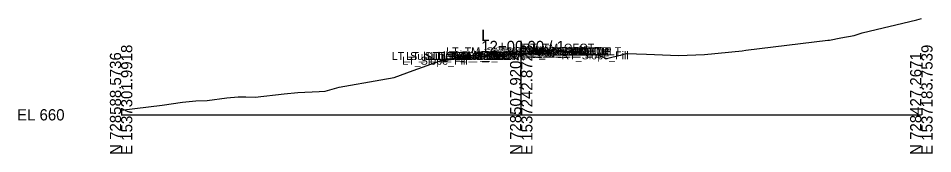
# Model space of a CAD drawing. Extents: x -26 to 1203, y -10 to 9522.
# Drawn here: x -25.7 to 202.8, y 1990.3 to 2024.1 of the extents above; entities that cross this region are included whole.
import ezdxf

# ---------------------------------------------------------------- set-up
doc = ezdxf.new("R2010")
doc.units = 0
for name, color, linetype in [('Default', 7, 'Continuous'), ('Exist Cross Section Cell', 7, 'Continuous'), ('Exist XS Center Line Elevation Label', 7, 'Continuous'), ('Exist XS Ground Line', 7, 'Continuous'), ('Old_Level_63', 7, 'Continuous'), ('Prop CMT Pvmt Surface', 7, 'Continuous'), ('Prop CMT Pvmt Surface Shoulder', 7, 'Continuous'), ('Prop CMT Slope Grass', 7, 'Continuous'), ('Prop Superelevation  Arrow CELL', 7, 'Continuous'), ('Prop XS EOT Tick Mark', 7, 'Continuous'), ('Prop XS SE Text', 7, 'Continuous'), ('Prop XS Side Slope Text', 7, 'Continuous')]:
    doc.layers.add(name, color=color, linetype=linetype)

msp = doc.modelspace()

# ---------------------------------------------------------------- linework, layer by layer
at = {"layer": 'Exist Cross Section Cell'}
for p, q in [((100, 2000), (100, 2018.45)), ((0, 2000), (100, 2000)), ((100, 2000), (200, 2000))]:
    msp.add_line(p, q, dxfattribs=at)
at = {"layer": 'Exist XS Ground Line'}
msp.add_lwpolyline([(0, 2001.15), (10.28, 2002.41), (15.35, 2003.13), (18.64, 2003.49), (21.47, 2003.54), (26.4, 2004.24), (29.25, 2004.52), (31.21, 2004.47), (33.53, 2004.44), (40.79, 2005.2), (44.21, 2005.59), (49.47, 2005.79), (50.98, 2005.87), (54.46, 2006.89), (64.89, 2008.71), (68.27, 2009.33), (72.98, 2011.01), (79.75, 2013.49), (83.92, 2014), (87, 2014.4), (98.28, 2015.01), (99.53, 2015.08), (100, 2015.1), (100.83, 2015.13), (112.48, 2015.61), (119.49, 2014.85), (119.59, 2014.84), (119.6, 2014.83), (121.32, 2014.04), (125.1, 2014.98), (126.27, 2015.26), (131.34, 2015.1), (139.32, 2014.79), (145.84, 2015.07), (155.2, 2015.97), (156.16, 2016.13), (176.6, 2018.62), (177.06, 2018.64), (179.87, 2019.16), (183.22, 2019.81), (185.18, 2020.44), (198.88, 2023.7), (200, 2024.06)], dxfattribs=at)
at = {"layer": 'Prop CMT Pvmt Surface'}
for points in [[(100, 2015.36), (109.4, 2015.75)], [(100, 2015.36), (90.3, 2014.84)]]:
    msp.add_lwpolyline(points, dxfattribs=at)
at = {"layer": 'Prop CMT Pvmt Surface Shoulder'}
for points in [[(109.4, 2015.75), (112.49, 2015.87)], [(90.3, 2014.84), (87.06, 2014.67)]]:
    msp.add_lwpolyline(points, dxfattribs=at)
at = {"layer": 'Prop CMT Slope Grass'}
for points in [[(112.49, 2015.87), (119.59, 2014.84)], [(87.06, 2014.67), (79.75, 2013.49)]]:
    msp.add_lwpolyline(points, dxfattribs=at)
at = {"layer": 'Prop Superelevation  Arrow CELL'}
for p, q in [((107.92, 2016.03), (101.93, 2015.77)), ((97.85, 2015.61), (91.86, 2015.35))]:
    msp.add_line(p, q, dxfattribs=at)
for points in [[(91.86, 2015.35), (93.34, 2015.92), (93.01, 2015.4)], [(101.93, 2015.77), (103.41, 2016.33), (103.09, 2015.82)]]:
    msp.add_lwpolyline(points, close=True, dxfattribs=at)
at = {"layer": 'Prop XS EOT Tick Mark'}
for points in [[(90.3, 2014.84), (90.3, 2015.84)], [(109.4, 2015.75), (109.4, 2016.75)]]:
    msp.add_lwpolyline(points, dxfattribs=at)

# ---------------------------------------------------------------- texts
at = {"layer": 'Default'}
msp.add_text('-', height=0.0001, dxfattribs=at).set_placement((0, 2000))
msp.add_text('-', height=0.0001, dxfattribs=at).set_placement((0, 2000))
msp.add_text('-', height=0.0001, dxfattribs=at).set_placement((0, 2000))
at = {"layer": 'Exist Cross Section Cell'}
for s, p in [('L', (90, 2018.45)), ('12+00.00 / 1', (90, 2015.65)), ('EL 660', (-26, 1998.6))]:
    msp.add_text(s, height=2.8, dxfattribs=at).set_placement(p)
for s, p in [('E 1537301.9918', (2.8, 1990)), ('E 1537242.8728', (102.8, 1990)), ('E 1537183.7539', (202.8, 1990)), ('N 728588.5736', (0, 1990)), ('N 728507.9204', (100, 1990)), ('N 728427.2671', (200, 1990))]:
    msp.add_text(s, height=2.8, rotation=90, dxfattribs=at).set_placement(p)
at = {"layer": 'Exist XS Center Line Elevation Label'}
msp.add_text('675.10', height=0.75, dxfattribs=at).set_placement((98.5, 2014.03))
at = {"layer": 'Old_Level_63'}
for s, p in [('LT_Sub_Trench_Out_DLT', (67.63, 2013.67)), ('LT_Sub_Trench_Out', (71.27, 2013.67)), ('LT_GS_OS_CTL', (76.43, 2013.67)), ('LT_PS3_OEOP', (77.3, 2013.67)), ('LT_PS2_OEOP', (77.3, 2013.67)), ('LT_PS1_OEOP', (77.86, 2013.67)), ('LT_Sub_OEOT', (80.38, 2013.84)), ('LT_PV3_OEOT', (80.47, 2013.84)), ('LT_PV2_OEOT', (80.47, 2013.84)), ('LT_PV1_OEOT', (81.04, 2013.84)), ('LT_TM_OEOT', (81.24, 2014.84)), ('LT_Sub_OEEOP', (89.21, 2014.36)), ('RT_PV2_OEEOP', (89.26, 2014.36)), ('RT_PV3_OEEOP', (89.26, 2014.36)), ('PV1_PGL_W', (92.58, 2014.36)), ('RT_Sub_Trench_Out_DLT', (93.01, 2014.87)), ('PV1_PGL', (94.47, 2014.36)), ('RT_Sub_Trench_Out', (96.65, 2014.87)), ('RT_PS3_Shelf_Out', (98.43, 2014.87)), ('RT_Sub_OEOT', (99.43, 2014.75)), ('RT_PV2_OEOT', (99.53, 2014.75)), ('RT_PV3_OEOT', (99.53, 2014.75)), ('RT_PV1_OEOT', (100.09, 2014.75)), ('RT_TM_OEOT', (100.3, 2015.75)), ('RT_GS_OS_CTL', (101.81, 2014.87)), ('RT_PS2_OEOP', (102.68, 2014.87)), ('RT_PS1_OEOP', (103.25, 2014.87)), ('RT_Slope_Fill', (110.06, 2013.84)), ('LT_Slope_Fill', (70.27, 2012.49))]:
    msp.add_text(s, height=2, dxfattribs=at).set_placement(p)
at = {"layer": 'Prop XS SE Text'}
for rotation, p in [(3.069, (93.71, 2015.7)), (2.3238, (103.65, 2016.15))]:
    msp.add_text('EXIST.', height=1, rotation=rotation, dxfattribs=at).set_placement(p)
at = {"layer": 'Prop XS Side Slope Text'}
for s, rotation, p in [('6.17:1', 9.2109, (81.65, 2014.55)), ('6.87:1', 351.7132, (114.39, 2016.35))]:
    msp.add_text(s, height=1, rotation=rotation, dxfattribs=at).set_placement(p)

doc.saveas('drawing.dxf')
